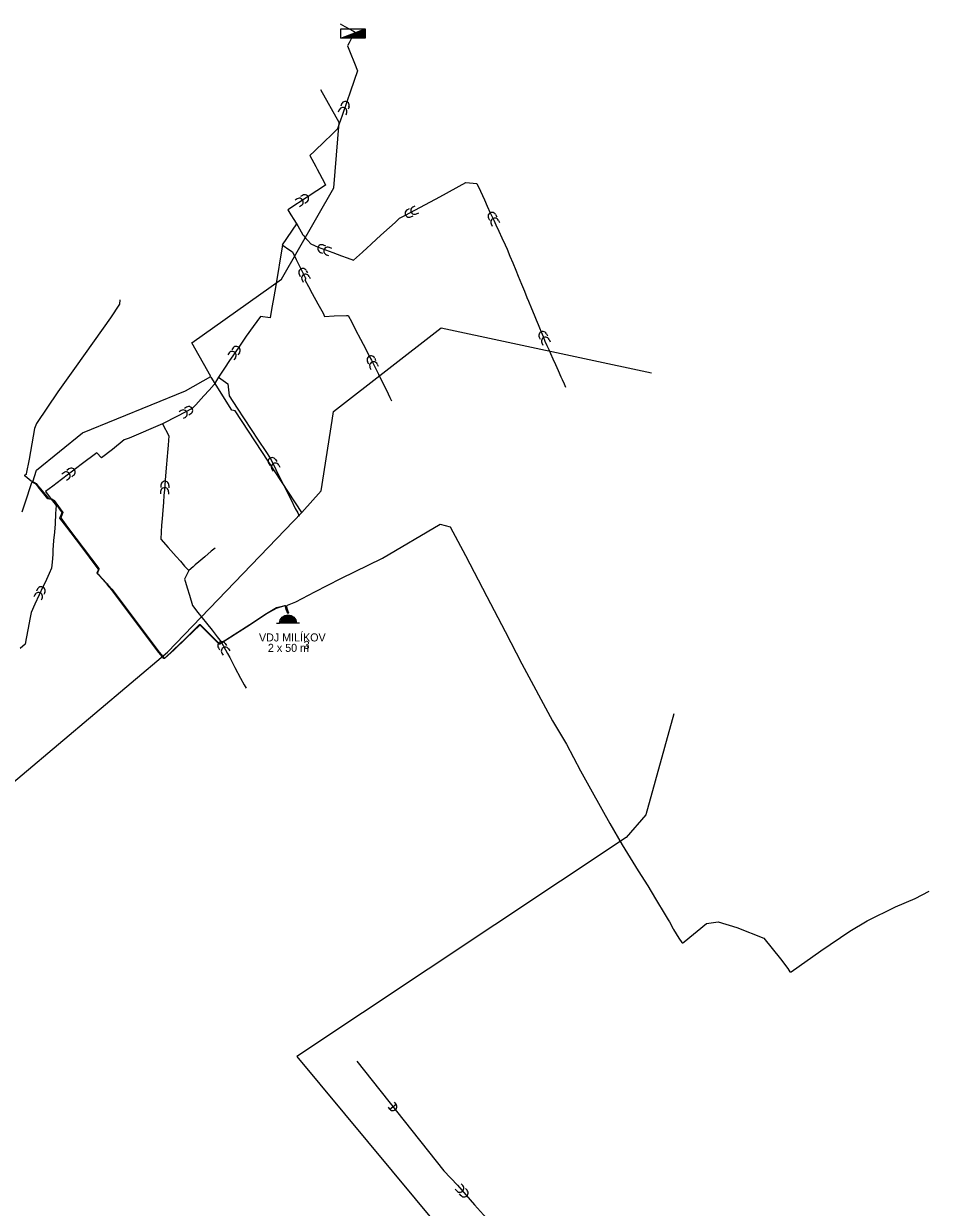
# Model space of a CAD drawing. Extents: x -445050 to -433212, y -1145927 to -1129778.
# Drawn here: x -442201 to -441070, y -1131257 to -1129778 of the extents above; entities that cross this region are included whole.
import ezdxf

# ---------------------------------------------------------------- set-up
doc = ezdxf.new("R2010")
doc.units = 0
for name, color, linetype in [('Vrstva 14', 7, 'Continuous'), ('Vrstva 16', 7, 'Continuous'), ('Vrstva 3', 7, 'Continuous'), ('Vrstva 32', 7, 'Continuous'), ('Vrstva 35', 7, 'Continuous'), ('Vrstva 41', 7, 'Continuous')]:
    doc.layers.add(name, color=color, linetype=linetype)

msp = doc.modelspace()

# ---------------------------------------------------------------- linework, layer by layer
at = {"layer": 'Vrstva 16'}
for p, q in [((-441885.2, -1130527.1), (-441881.2, -1130527.1)), ((-441885.2, -1130527.1), (-441881.2, -1130527.1)), ((-441856.4, -1130527.1), (-441860.3, -1130527.1)), ((-441856.4, -1130527.1), (-441860.3, -1130527.1))]:
    msp.add_line(p, q, dxfattribs=at)
for points in [[(-441881.2, -1130527.1), (-441880.4, -1130523.1), (-441878.1, -1130519.8), (-441874.8, -1130517.5), (-441870.8, -1130516.7), (-441866.8, -1130517.5), (-441863.4, -1130519.8), (-441861.1, -1130523.1), (-441860.3, -1130527.1)], [(-441881.2, -1130527.1), (-441880.4, -1130523.1), (-441878.1, -1130519.8), (-441874.8, -1130517.5), (-441870.8, -1130516.7), (-441866.8, -1130517.5), (-441863.4, -1130519.8), (-441861.1, -1130523.1), (-441860.3, -1130527.1)], [(-441880, -1130526.1), (-441879.5, -1130523.5), (-441877.4, -1130520.5), (-441874.4, -1130518.4), (-441870.8, -1130517.7), (-441867.1, -1130518.4), (-441864.1, -1130520.5), (-441862, -1130523.5), (-441861.5, -1130526.1)], [(-441880, -1130526.1), (-441879.5, -1130523.5), (-441877.4, -1130520.5), (-441874.4, -1130518.4), (-441870.8, -1130517.7), (-441867.1, -1130518.4), (-441864.1, -1130520.5), (-441862, -1130523.5), (-441861.5, -1130526.1)], [(-441878.8, -1130525.1), (-441878.5, -1130523.9), (-441876.7, -1130521.2), (-441874, -1130519.4), (-441870.8, -1130518.7), (-441867.5, -1130519.4), (-441864.8, -1130521.2), (-441863, -1130523.9), (-441862.7, -1130525.1)], [(-441878.8, -1130525.1), (-441878.5, -1130523.9), (-441876.7, -1130521.2), (-441874, -1130519.4), (-441870.8, -1130518.7), (-441867.5, -1130519.4), (-441864.8, -1130521.2), (-441863, -1130523.9), (-441862.7, -1130525.1)], [(-441877.5, -1130524.1), (-441876, -1130521.9), (-441873.6, -1130520.3), (-441870.8, -1130519.7), (-441867.9, -1130520.3), (-441865.5, -1130521.9), (-441864, -1130524.1)], [(-441877.5, -1130524.1), (-441876, -1130521.9), (-441873.6, -1130520.3), (-441870.8, -1130519.7), (-441867.9, -1130520.3), (-441865.5, -1130521.9), (-441864, -1130524.1)], [(-441875.6, -1130523.1), (-441875.3, -1130522.6), (-441873.2, -1130521.3), (-441870.8, -1130520.8), (-441868.3, -1130521.3), (-441866.2, -1130522.6), (-441865.9, -1130523.1)], [(-441875.6, -1130523.1), (-441875.3, -1130522.6), (-441873.2, -1130521.3), (-441870.8, -1130520.8), (-441868.3, -1130521.3), (-441866.2, -1130522.6), (-441865.9, -1130523.1)], [(-441872.5, -1130522.1), (-441870.8, -1130521.8), (-441869, -1130522.1)], [(-441872.5, -1130522.1), (-441870.8, -1130521.8), (-441869, -1130522.1)]]:
    msp.add_lwpolyline(points, close=True, dxfattribs=at)
at = {"layer": 'Vrstva 3'}
for points in [[(-442184.6, -1130336.3), (-442127.1, -1130289.5), (-441998.7, -1130236.9), (-441967.2, -1130219.2), (-441990.9, -1130177.1), (-441878.7, -1130097.6), (-441813.7, -1129983.6), (-441806.9, -1129901.8), (-441829.8, -1129861.2)], [(-442080.7, -1130123.5), (-442081.3, -1130128.7), (-442092.4, -1130146), (-442135.3, -1130206.3), (-442158.3, -1130238.5), (-442184.8, -1130278), (-442187.1, -1130284.2), (-442193.8, -1130322.3), (-442197.6, -1130340.9), (-442197.7, -1130341.4), (-442199.6, -1130342.3), (-442199.8, -1130343.1), (-442199.9, -1130343.4)], [(-442639.4, -1130985.4), (-442636.3, -1130987.9), (-442568.1, -1130946.4), (-442547.5, -1130933.4), (-442527.4, -1130927.1), (-442481.3, -1130902.1), (-442461.8, -1130915.5), (-442444, -1130928.2), (-442432, -1130939.4), (-442338.4, -1130842.5), (-442282, -1130781.8), (-442258.5, -1130763), (-442251.9, -1130757.7), (-442248.4, -1130755), (-442021.4, -1130563.5), (-441853.6, -1130388.9), (-441829.4, -1130362.1), (-441815.6, -1130274.2), (-441814.1, -1130262.8), (-441679.4, -1130158.4), (-441417.1, -1130214.5)], [(-441853.6, -1130388.9), (-441936.6, -1130262.2), (-441940.7, -1130261.3), (-441966.7, -1130220.1)], [(-442199.8, -1130343.1), (-442199.5, -1130343.2), (-442198.8, -1130343.4), (-442191.3, -1130349.5), (-442190.3, -1130350.1), (-442185.2, -1130352.9), (-442182.6, -1130356.3), (-442182, -1130357.1), (-442169.9, -1130371.4), (-442168, -1130372), (-442164.8, -1130372.2), (-442162.6, -1130373.9), (-442152, -1130388.9), (-442154.5, -1130395.9), (-442146.1, -1130407.4), (-442106.9, -1130459.2), (-442106.8, -1130460), (-442108.6, -1130464.5), (-442108.5, -1130465.1), (-442108, -1130465.6), (-442107.1, -1130466.5), (-442106.4, -1130467.3), (-442097.5, -1130477.3), (-442096.6, -1130478.3), (-442095.8, -1130479.2), (-442094.9, -1130480.2), (-442090.5, -1130485), (-442064, -1130520.3), (-442033.2, -1130561.3), (-442025.4, -1130571.1), (-442024.6, -1130570.9), (-442013.6, -1130560.7), (-441999.1, -1130546.7), (-441981.3, -1130528.9), (-441980.3, -1130528.9), (-441956.7, -1130552.6), (-441955.9, -1130552.7), (-441948.4, -1130548.2), (-441918.4, -1130528.8), (-441897.7, -1130515.1), (-441885.1, -1130507.8), (-441874.4, -1130505.2), (-441873.3, -1130506.2), (-441871.9, -1130510.6), (-441870.5, -1130515.1)], [(-442189.3, -1130350.7), (-442184.6, -1130336.3)], [(-441871.2, -1130515.4), (-441872.9, -1130510.1), (-441874.1, -1130506.5), (-441875, -1130505.7), (-441885.5, -1130508.8), (-441897.5, -1130515.8), (-441918.1, -1130529.2), (-441955.8, -1130553.6), (-441956.6, -1130553.5), (-441980, -1130530.2), (-441980.8, -1130529.9), (-441998.4, -1130546.6), (-442013, -1130560.7), (-442024.9, -1130571.5), (-442025.9, -1130571.6), (-442033.5, -1130561.8), (-442090.8, -1130485.5), (-442096, -1130479.5), (-442097.2, -1130478.2), (-442097.6, -1130477.5), (-442098.9, -1130476.2), (-442106.6, -1130467.7), (-442107.1, -1130467.1), (-442107.7, -1130466.4), (-442108.4, -1130465.7), (-442108.9, -1130465), (-442108.9, -1130464.2), (-442107.5, -1130461), (-442107.4, -1130460.1), (-442107.6, -1130459.3), (-442129.4, -1130430.4), (-442146.9, -1130407.4), (-442155.4, -1130396), (-442152.7, -1130389.1), (-442162.9, -1130374.1), (-442164.6, -1130373.1), (-442168.4, -1130372.4), (-442170.5, -1130371.9), (-442182.7, -1130357.1), (-442185.8, -1130353.3), (-442189.4, -1130351.4), (-442189.8, -1130351.4), (-442190.9, -1130352.1), (-442192, -1130354.7), (-442198.6, -1130374.9), (-442202.9, -1130388.5)], [(-441869.6, -1130514.8), (-441870.8, -1130511.3), (-441872.6, -1130505.9), (-441871.4, -1130504.8), (-441861.1, -1130500.6), (-441837.3, -1130488.3), (-441804.7, -1130471.6), (-441752.9, -1130446.2), (-441681, -1130403.7), (-441668.4, -1130407.1), (-441649.3, -1130442.8), (-441622.7, -1130494.1), (-441599.8, -1130537.5), (-441578.8, -1130578.2), (-441540.5, -1130649.1), (-441523.3, -1130678.6), (-441505.6, -1130711.9), (-441491.2, -1130738.1), (-441468.9, -1130777.6), (-441453.6, -1130804), (-441433.6, -1130836.6), (-441421.7, -1130855.4), (-441411.9, -1130871.6), (-441399.9, -1130891.5), (-441396.1, -1130898), (-441394.7, -1130900.4), (-441389.9, -1130908.9), (-441389.4, -1130909.8), (-441383.1, -1130920.6), (-441379.4, -1130926.1), (-441378.8, -1130926.5), (-441378.1, -1130926.5), (-441376.9, -1130925.9), (-441376.3, -1130925.4), (-441348.3, -1130902.6), (-441333.7, -1130900.4), (-441310.6, -1130907.6), (-441277, -1130920.6), (-441256.1, -1130946.4), (-441246.9, -1130958.6), (-441244.2, -1130962.6), (-441243.5, -1130962.9), (-441242.8, -1130962.8), (-441205.5, -1130936.7), (-441169.6, -1130912.1), (-441147.8, -1130899.3), (-441112.3, -1130881.8), (-441087.8, -1130871), (-441070.3, -1130862)], [(-441389.1, -1130640.5), (-441424.2, -1130766.8), (-441448.8, -1130794.9), (-441859.7, -1131068.7), (-441652.5, -1131317.9)]]:
    msp.add_lwpolyline(points, dxfattribs=at)
at = {"layer": 'Vrstva 32'}
for p, q in [((-441806.9, -1129886.2), (-441808, -1129889)), ((-441803.9, -1129878.8), (-441805, -1129881.6)), ((-441797.6, -1129889.9), (-441798.7, -1129892.7)), ((-441794.6, -1129882.5), (-441795.7, -1129885.3)), ((-441852.7, -1129992.9), (-441855.2, -1129994.5)), ((-441859.4, -1129997.2), (-441862, -1129998.9)), ((-441854.1, -1130005.7), (-441856.6, -1130007.3)), ((-441847.3, -1130001.4), (-441849.8, -1130003)), ((-441721.9, -1130010.8), (-441719.2, -1130009.4)), ((-441714.7, -1130007.1), (-441712.1, -1130005.8)), ((-441717.3, -1130019.7), (-441714.6, -1130018.3)), ((-441710.2, -1130016), (-441707.5, -1130014.7)), ((-441620.6, -1130021.2), (-441619.4, -1130023.9)), ((-441611.6, -1130017), (-441610.3, -1130019.7)), ((-441608.2, -1130024.2), (-441606.9, -1130026.9)), ((-441617.2, -1130028.5), (-441616, -1130031.2)), ((-441826.7, -1130054.9), (-441824, -1130056)), ((-441830.4, -1130064.2), (-441827.6, -1130065.3)), ((-441822.9, -1130067.1), (-441820.1, -1130068.2)), ((-441819.3, -1130057.8), (-441816.5, -1130058.9)), ((-441856.9, -1130091.5), (-441855.5, -1130094.1)), ((-441853.3, -1130098.6), (-441851.9, -1130101.3)), ((-441848, -1130087), (-441846.6, -1130089.6)), ((-441844.3, -1130094.1), (-441843, -1130096.8)), ((-441557.3, -1130170), (-441556, -1130172.7)), ((-441548.2, -1130165.7), (-441546.9, -1130168.4)), ((-441544.8, -1130172.9), (-441543.5, -1130175.7)), ((-441939.3, -1130183.4), (-441941.1, -1130185.7)), ((-441553.8, -1130177.2), (-441552.5, -1130179.9)), ((-441944.3, -1130189.6), (-441946.1, -1130192)), ((-441936.5, -1130195.9), (-441938.3, -1130198.2)), ((-441931.5, -1130189.7), (-441933.3, -1130192)), ((-441771.8, -1130200.5), (-441770.5, -1130203.2)), ((-441762.6, -1130196.4), (-441761.4, -1130199.1)), ((-441768.5, -1130207.8), (-441767.3, -1130210.5)), ((-441759.4, -1130203.7), (-441758.1, -1130206.4)), ((-442004.1, -1130261.6), (-442006.7, -1130263.2)), ((-441997.3, -1130257.5), (-441999.8, -1130259)), ((-441998.9, -1130270.2), (-442001.5, -1130271.7)), ((-441992.1, -1130266), (-441994.6, -1130267.6)), ((-442144.5, -1130334.6), (-442146.8, -1130336.4)), ((-441894.9, -1130327.9), (-441893.4, -1130330.5)), ((-441890.9, -1130334.8), (-441889.4, -1130337.4)), ((-441886.3, -1130322.9), (-441884.8, -1130325.5)), ((-441882.3, -1130329.8), (-441880.8, -1130332.4)), ((-442150.8, -1130339.4), (-442153.2, -1130341.2)), ((-442144.8, -1130347.4), (-442147.2, -1130349.2)), ((-442138.4, -1130342.6), (-442140.8, -1130344.4)), ((-442029.8, -1130362.8), (-442029.9, -1130365.8)), ((-442029.5, -1130354.8), (-442029.6, -1130357.8)), ((-442019.8, -1130363.2), (-442020, -1130366.2)), ((-442019.5, -1130355.2), (-442019.6, -1130358.2)), ((-442186.8, -1130491.8), (-442188.1, -1130494.5)), ((-442183.5, -1130484.6), (-442184.7, -1130487.3)), ((-442177.7, -1130496), (-442179, -1130498.7)), ((-442174.4, -1130488.8), (-442175.6, -1130491.5)), ((-441949.3, -1130552.7), (-441947.7, -1130555.2)), ((-441957.7, -1130558.1), (-441956.1, -1130560.6)), ((-441953.3, -1130564.8), (-441951.7, -1130567.4)), ((-441944.9, -1130559.4), (-441943.3, -1130561.9)), ((-441660, -1131236.4), (-441662, -1131234.1)), ((-441652.6, -1131229.7), (-441654.6, -1131227.5)), ((-441647.3, -1131235.7), (-441649.2, -1131233.5)), ((-441654.7, -1131242.4), (-441656.7, -1131240.1))]:
    msp.add_line(p, q, dxfattribs=at)
for points in [[(-441805.6, -1129778.5), (-441799.8, -1129781.8), (-441789.2, -1129787.8), (-441785.9, -1129789.8)], [(-441791.7, -1129796.7), (-441794.5, -1129802.3), (-441796.1, -1129805.4), (-441796.4, -1129806.2), (-441793, -1129814.6), (-441787.8, -1129827.8), (-441783.9, -1129837.2), (-441792.8, -1129862.6), (-441797.4, -1129876), (-441803.3, -1129893.3), (-441807.3, -1129904.9), (-441809.2, -1129909.9), (-441816.5, -1129917.2), (-441825.3, -1129925.5), (-441837.9, -1129937.6), (-441843.6, -1129943.2), (-441836.1, -1129957), (-441834.4, -1129960.2), (-441825.3, -1129977.3), (-441823.8, -1129980.1), (-441845.8, -1129994.5), (-441871, -1130010.9), (-441867.1, -1130017.1), (-441863.4, -1130022.9), (-441858.7, -1130030.8), (-441858.7, -1130030.8), (-441852.1, -1130042.4), (-441851.2, -1130043.4), (-441848.4, -1130046.7), (-441845.9, -1130049.3), (-441842.3, -1130053.4), (-441833.2, -1130057.7), (-441824, -1130061.1), (-441815, -1130064.3), (-441804.2, -1130068.3), (-441797.1, -1130070.9), (-441789.2, -1130073.8), (-441777.9, -1130063.7), (-441772.1, -1130058.4), (-441767.3, -1130054.1), (-441759.7, -1130047.1), (-441751.1, -1130039.3), (-441737.2, -1130026.7), (-441731.5, -1130021.5), (-441724, -1130017.6), (-441681.4, -1129994.6), (-441648.7, -1129977), (-441635.1, -1129978.2), (-441630.7, -1129987.5), (-441625.7, -1129998.5), (-441622, -1130006.3), (-441618.3, -1130014.6), (-441614, -1130023.9), (-441611.2, -1130029.9), (-441607.6, -1130037.8), (-441603.9, -1130045.8), (-441599.8, -1130054.7), (-441597.3, -1130060.2), (-441593.7, -1130068.7), (-441590.2, -1130077.2), (-441586.5, -1130086.3), (-441583.5, -1130093.8), (-441579.2, -1130103.9), (-441575.7, -1130112.6), (-441572.5, -1130120.6), (-441570.5, -1130125.1), (-441566.7, -1130134.4), (-441563.5, -1130142.3), (-441561, -1130148.5), (-441558.6, -1130154.4), (-441556.9, -1130158.3), (-441554.9, -1130163.3), (-441552.4, -1130169.4), (-441550, -1130174.9), (-441547.6, -1130180.3), (-441545.3, -1130185.5), (-441543, -1130190.4), (-441540.1, -1130197.3), (-441537, -1130204.3), (-441533.7, -1130211.6), (-441530.3, -1130219.5), (-441528.7, -1130222.9), (-441526.2, -1130228.5), (-441524.3, -1130232.7)], [(-441860.2, -1130028.3), (-441865.4, -1130036.2), (-441872.6, -1130046.8), (-441877.9, -1130054.6), (-441868.6, -1130061.2), (-441865.2, -1130063.5), (-441860.5, -1130072.9), (-441854.7, -1130084.8), (-441851.3, -1130091.2), (-441849.2, -1130095.6), (-441848.7, -1130096.5), (-441849.7, -1130098.4), (-441845.2, -1130106.6), (-441840.6, -1130115.3), (-441833.4, -1130128.4), (-441827.1, -1130139.9), (-441825.1, -1130144.1), (-441813.1, -1130143.6), (-441797.8, -1130143), (-441795.7, -1130142.8), (-441791.3, -1130151.5), (-441786.4, -1130160.9), (-441780.3, -1130172.5), (-441773.7, -1130185.2), (-441769.3, -1130193.8), (-441766.5, -1130198.8), (-441763.3, -1130205.4), (-441758, -1130216.1), (-441753, -1130226.5), (-441748.4, -1130235.6), (-441745.7, -1130241), (-441743.6, -1130245.5), (-441741.5, -1130249.7)], [(-441877.7, -1130054.6), (-441886.4, -1130108), (-441889.5, -1130124.3), (-441890.9, -1130133), (-441893, -1130145.8), (-441905.3, -1130144.4), (-441914.1, -1130156.6), (-441922.9, -1130169), (-441932.2, -1130182.6), (-441939.6, -1130193.4), (-441943.8, -1130199.3), (-441949.9, -1130208.7), (-441957.4, -1130219.8), (-441945.8, -1130228.3)], [(-441957.4, -1130219.8), (-441960, -1130224.3), (-441962.9, -1130229.1), (-441969.3, -1130236.2), (-441975.9, -1130243.4), (-441985.9, -1130254.5), (-441990.4, -1130259.1)], [(-441945.8, -1130228.3), (-441944.3, -1130243.5), (-441934.3, -1130258.9), (-441916.7, -1130285.2), (-441907.9, -1130298.5), (-441898.3, -1130313), (-441893.1, -1130321.1), (-441888.4, -1130330)], [(-441990.4, -1130259.1), (-442008.6, -1130268.6), (-442027.5, -1130278.3), (-442019.7, -1130293.4), (-442020.5, -1130304.9), (-442021.3, -1130314), (-442021.7, -1130319.2), (-442022.8, -1130333.4), (-442024.2, -1130348.7), (-442024.5, -1130355)], [(-442027.5, -1130278.3), (-442068.9, -1130296), (-442075.3, -1130298.4), (-442089.9, -1130310.2), (-442103.4, -1130320.8), (-442109.5, -1130314.4), (-442128.8, -1130329.2), (-442139.8, -1130337.3), (-442144.6, -1130341.1), (-442153.4, -1130347.8), (-442164.4, -1130356.2), (-442168.9, -1130359.4), (-442173.3, -1130362.8), (-442167.5, -1130370.8), (-442160.3, -1130380.4), (-442161, -1130390.4), (-442161.6, -1130403.1), (-442162.4, -1130413.7), (-442163.3, -1130424.1), (-442164.2, -1130436), (-442164.4, -1130441.4), (-442165.3, -1130451.2), (-442165.8, -1130458.5), (-442168.9, -1130465.2), (-442172.4, -1130472.7), (-442174.1, -1130476.4), (-442176.8, -1130482.1), (-442181.5, -1130492), (-442186.9, -1130503.6), (-442191.5, -1130513.8), (-442193, -1130522.1), (-442195.1, -1130533.6), (-442197.6, -1130546.6), (-442198.8, -1130553.6), (-442205.1, -1130558.8)], [(-441888.5, -1130330), (-441883.4, -1130340.6), (-441876.8, -1130353.7), (-441867.4, -1130372.2), (-441861.7, -1130383.9), (-441858.7, -1130389.6), (-441857, -1130393.6)], [(-442024.5, -1130355), (-442025.1, -1130361), (-442025.7, -1130367.5), (-442026.2, -1130376.5), (-442027, -1130386.3), (-442027.9, -1130397), (-442028.5, -1130405), (-442029, -1130413.3), (-442029.7, -1130422.2), (-442020.4, -1130432.7), (-442010.4, -1130444.1), (-442005, -1130450), (-442000, -1130455.9), (-441994.7, -1130461.6)], [(-441961.8, -1130433.4), (-441966.6, -1130437.5), (-441974.7, -1130444.4), (-441982.1, -1130450.7), (-441986.5, -1130454.4), (-441989.3, -1130456.8), (-441994.7, -1130461.6)], [(-441994.7, -1130461.6), (-441998.4, -1130469), (-442000.1, -1130472.2), (-441998.9, -1130476.1), (-441996.6, -1130483.3), (-441993.9, -1130492.5), (-441990, -1130505.4), (-441983.3, -1130513.8), (-441972.5, -1130527.3), (-441965.6, -1130536.1), (-441959.1, -1130544.2), (-441954.1, -1130550.4), (-441946.2, -1130565.3), (-441943.5, -1130570.2), (-441937, -1130582.7), (-441930, -1130595.8), (-441925.4, -1130604.3), (-441923.2, -1130608.6)], [(-441676.4, -1131211.3), (-441659.3, -1131229.1), (-441638.1, -1131254), (-441619.4, -1131274.6)]]:
    msp.add_lwpolyline(points, dxfattribs=at)
for centre, start, end in [((-441799.3, -1129880.6), 338.2077, 158.2088), ((-441802.2, -1129888.1), 338.2077, 158.2088), ((-441850, -1129997.1), 302.5841, 122.5852), ((-441856.7, -1130001.5), 302.5841, 122.5852), ((-441712.5, -1130011.6), 117.2982, 297.2993), ((-441719.6, -1130015.3), 117.2982, 297.2993), ((-441616.1, -1130019.1), 25.1744, 205.1755), ((-441612.7, -1130026.3), 25.1744, 205.1755), ((-441828.6, -1130059.5), 68.6864, 248.6875), ((-441821.1, -1130062.5), 68.6864, 248.6875), ((-441852.4, -1130089.2), 26.8318, 206.8329), ((-441848.8, -1130096.4), 26.8318, 206.8329), ((-441552.7, -1130167.9), 25.313, 205.3141), ((-441549.3, -1130175.1), 25.313, 205.3141), ((-441940.4, -1130192.8), 321.2503, 141.2514), ((-441935.4, -1130186.5), 321.2503, 141.2514), ((-441767.2, -1130198.4), 24.2027, 204.2038), ((-441763.9, -1130205.7), 24.2027, 204.2038), ((-442001.5, -1130265.9), 301.3083, 121.3093), ((-441994.7, -1130261.7), 301.3083, 121.3093), ((-441890.6, -1130325.4), 30.1484, 210.1495), ((-442141.4, -1130338.6), 306.8961, 126.8972), ((-441886.6, -1130332.3), 30.1484, 210.1495), ((-442147.8, -1130343.4), 306.8961, 126.8972), ((-442024.5, -1130355), 357.5568, 177.5579), ((-442024.8, -1130363), 357.5568, 177.5579), ((-442178.9, -1130486.7), 335.1178, 155.1188), ((-442182.3, -1130493.9), 335.1178, 155.1188), ((-441953.5, -1130555.4), 32.8593, 212.8604), ((-441949.1, -1130562.1), 32.8593, 212.8604), ((-441656.3, -1131233.1), 221.6612, 41.6623), ((-441651, -1131239), 221.6612, 41.6623)]:
    msp.add_arc(centre, 5, start, end, dxfattribs=at)
at = {"layer": 'Vrstva 35'}
for p, q in [((-441743.7, -1131134.3), (-441745.5, -1131131.9)), ((-441743.7, -1131134.3), (-441735.8, -1131128.1)), ((-441735.8, -1131128.1), (-441737.7, -1131125.7))]:
    msp.add_line(p, q, dxfattribs=at)
msp.add_lwpolyline([(-441784.7, -1131074.4), (-441676.4, -1131211.3)], dxfattribs=at)
msp.add_arc((-441739.8, -1131131.2), 5, 218.3511, 38.3518, dxfattribs=at)
at = {"layer": 'Vrstva 41'}
msp.add_lwpolyline([(-441804.8, -1129796.7), (-441804.8, -1129784.7), (-441774.4, -1129784.7)], dxfattribs=at)
for points in [[(-441774.4, -1129784.7), (-441774.4, -1129796.7), (-441804.8, -1129796.7)], [(-441775.2, -1129785.9), (-441775.2, -1129795.9), (-441800.6, -1129795.9)], [(-441776, -1129787.1), (-441776, -1129795.1), (-441796.4, -1129795.1)], [(-441776.8, -1129788.2), (-441776.8, -1129794.3), (-441792.2, -1129794.3)], [(-441777.6, -1129789.4), (-441777.6, -1129793.5), (-441788, -1129793.5)], [(-441778.4, -1129790.6), (-441778.4, -1129792.7), (-441783.8, -1129792.7)]]:
    msp.add_lwpolyline(points, close=True, dxfattribs=at)

# ---------------------------------------------------------------- texts
at = {"layer": 'Vrstva 14'}
msp.add_text('3', height=10, dxfattribs=at).set_placement((-441851.2, -1130559.4))
at = {"layer": 'Vrstva 16'}
for s, p in [('VDJ MILÍKOV ', (-441907, -1130550.1)), ('   2 x 50 m', (-441907, -1130563.1))]:
    msp.add_text(s, height=10, dxfattribs=at).set_placement(p)

doc.saveas('drawing.dxf')
